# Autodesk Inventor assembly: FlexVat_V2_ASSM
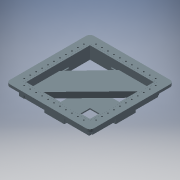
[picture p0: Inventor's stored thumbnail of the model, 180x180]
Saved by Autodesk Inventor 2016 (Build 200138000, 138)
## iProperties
Created: 2015-11
Part Number: FlexVat_V2_ASSM
Document SubType Name: Assembly
Designer: John
Title: FlexVat_V2_ASSM.stp
Sending System: SIEMENS PLM Software NX 7.5
Preprocessor: ST-DEVELOPER v11
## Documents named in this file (5)
- D:\3D Printer Designs\John Ledden Designs\DLP Printer\V0-4\FlexVat2\FlexVat_V2_ASSM.iam
- D:\3D Printer Designs\John Ledden Designs\DLP Printer\V0-4\FlexVat2\Poly_Base.ipt
- D:\3D Printer Designs\John Ledden Designs\DLP Printer\V0-4\FlexVat2\VatWall2.ipt
- D:\3D Printer Designs\John Ledden Designs\DLP Printer\V0-4\FlexVat2\90degFixture.ipt
- D:\3D Printer Designs\John Ledden Designs\DLP Printer\V0-4\FlexVat2\FlexVat_V2_ASSM.ipt
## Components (7 placed, 7 different names)
1. Poly_Base_1001
2. VatWall2_1002
3. VatWall2_1003
4. VatWall2_1004
5. VatWall2_1005
6. 90degFixture_1006
7. FlexVat_V2_ASSM
